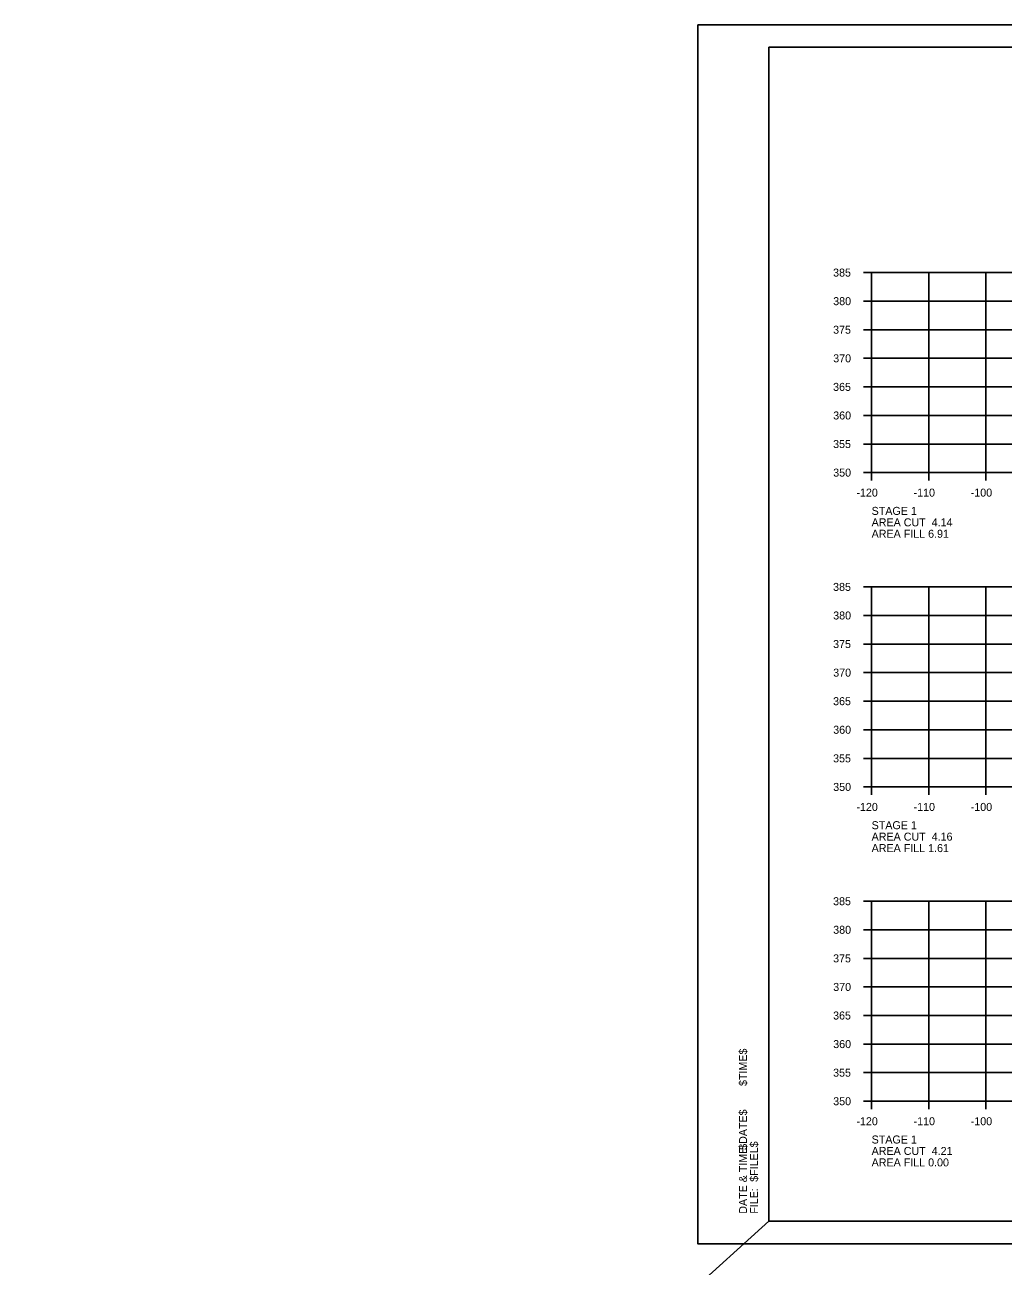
# Model space of a CAD drawing. Extents: x 1630712 to 1632516, y 782146 to 785403.
# Drawn here: x 1632064.8 to 1632236, y 783479.4 to 783696.6 of the extents above; entities that cross this region are included whole.
import ezdxf

# ---------------------------------------------------------------- set-up
doc = ezdxf.new("R2010")
doc.units = 0
for name, color, linetype in [('Default', 7, 'Continuous'), ('R_Axis', 7, 'Continuous'), ('R_Axis Annot', 7, 'Continuous'), ('R_Border', 7, 'Continuous'), ('R_Grid', 7, 'Continuous'), ('R_No Plot', 7, 'Continuous')]:
    doc.layers.add(name, color=color, linetype=linetype)

msp = doc.modelspace()

# ---------------------------------------------------------------- linework, layer by layer
at = {"layer": 'R_Axis'}
for p, q in [((1632211.56, 783653.28), (1632212.96, 783653.28)), ((1632212.96, 783618.28), (1632212.96, 783653.28)), ((1632211.56, 783648.28), (1632212.96, 783648.28)), ((1632211.56, 783643.28), (1632212.96, 783643.28)), ((1632211.56, 783638.28), (1632212.96, 783638.28)), ((1632211.56, 783633.28), (1632212.96, 783633.28)), ((1632211.56, 783628.28), (1632212.96, 783628.28)), ((1632211.56, 783623.28), (1632212.96, 783623.28)), ((1632211.56, 783618.28), (1632212.96, 783618.28)), ((1632212.96, 783618.28), (1632492.96, 783618.28)), ((1632212.96, 783616.88), (1632212.96, 783618.28)), ((1632222.96, 783616.88), (1632222.96, 783618.28)), ((1632232.96, 783616.88), (1632232.96, 783618.28)), ((1632211.56, 783598.28), (1632212.96, 783598.28)), ((1632212.96, 783563.28), (1632212.96, 783598.28)), ((1632211.56, 783593.28), (1632212.96, 783593.28)), ((1632211.56, 783588.28), (1632212.96, 783588.28)), ((1632211.56, 783583.28), (1632212.96, 783583.28)), ((1632211.56, 783578.28), (1632212.96, 783578.28)), ((1632211.56, 783573.28), (1632212.96, 783573.28)), ((1632211.56, 783568.28), (1632212.96, 783568.28)), ((1632211.56, 783563.28), (1632212.96, 783563.28)), ((1632212.96, 783563.28), (1632492.96, 783563.28)), ((1632212.96, 783561.88), (1632212.96, 783563.28)), ((1632222.96, 783561.88), (1632222.96, 783563.28)), ((1632232.96, 783561.88), (1632232.96, 783563.28)), ((1632211.56, 783543.28), (1632212.96, 783543.28)), ((1632212.96, 783508.28), (1632212.96, 783543.28)), ((1632211.56, 783538.28), (1632212.96, 783538.28)), ((1632211.56, 783533.28), (1632212.96, 783533.28)), ((1632211.56, 783528.28), (1632212.96, 783528.28)), ((1632211.56, 783523.28), (1632212.96, 783523.28)), ((1632211.56, 783518.28), (1632212.96, 783518.28)), ((1632211.56, 783513.28), (1632212.96, 783513.28)), ((1632211.56, 783508.28), (1632212.96, 783508.28)), ((1632212.96, 783508.28), (1632492.96, 783508.28)), ((1632212.96, 783506.88), (1632212.96, 783508.28)), ((1632222.96, 783506.88), (1632222.96, 783508.28)), ((1632232.96, 783506.88), (1632232.96, 783508.28))]:
    msp.add_line(p, q, dxfattribs=at)
at = {"layer": 'R_Border'}
for p, q in [((1632194.96, 783692.74), (1632511.14, 783692.74)), ((1632194.96, 783487.28), (1632194.96, 783692.74)), ((1632511.14, 783487.28), (1632194.96, 783487.28))]:
    msp.add_line(p, q, dxfattribs=at)
at = {"layer": 'R_Grid'}
for p, q in [((1632212.96, 783653.28), (1632492.96, 783653.28)), ((1632212.96, 783618.28), (1632212.96, 783653.28)), ((1632222.96, 783618.28), (1632222.96, 783653.28)), ((1632232.96, 783618.28), (1632232.96, 783653.28)), ((1632212.96, 783648.28), (1632492.96, 783648.28)), ((1632212.96, 783643.28), (1632492.96, 783643.28)), ((1632212.96, 783638.28), (1632492.96, 783638.28)), ((1632212.96, 783633.28), (1632492.96, 783633.28)), ((1632212.96, 783628.28), (1632492.96, 783628.28)), ((1632212.96, 783623.28), (1632492.96, 783623.28)), ((1632212.96, 783618.28), (1632492.96, 783618.28)), ((1632212.96, 783598.28), (1632492.96, 783598.28)), ((1632212.96, 783563.28), (1632212.96, 783598.28)), ((1632222.96, 783563.28), (1632222.96, 783598.28)), ((1632232.96, 783563.28), (1632232.96, 783598.28)), ((1632212.96, 783593.28), (1632492.96, 783593.28)), ((1632212.96, 783588.28), (1632492.96, 783588.28)), ((1632212.96, 783583.28), (1632492.96, 783583.28)), ((1632212.96, 783578.28), (1632492.96, 783578.28)), ((1632212.96, 783573.28), (1632492.96, 783573.28)), ((1632212.96, 783568.28), (1632492.96, 783568.28)), ((1632212.96, 783563.28), (1632492.96, 783563.28)), ((1632212.96, 783543.28), (1632492.96, 783543.28)), ((1632212.96, 783508.28), (1632212.96, 783543.28)), ((1632222.96, 783508.28), (1632222.96, 783543.28)), ((1632232.96, 783508.28), (1632232.96, 783543.28)), ((1632212.96, 783538.28), (1632492.96, 783538.28)), ((1632212.96, 783533.28), (1632492.96, 783533.28)), ((1632212.96, 783528.28), (1632492.96, 783528.28)), ((1632212.96, 783523.28), (1632492.96, 783523.28)), ((1632212.96, 783518.28), (1632492.96, 783518.28)), ((1632212.96, 783513.28), (1632492.96, 783513.28)), ((1632212.96, 783508.28), (1632492.96, 783508.28))]:
    msp.add_line(p, q, dxfattribs=at)
at = {"layer": 'R_No Plot'}
for p, q in [((1632182.56, 783696.63), (1632515.9, 783696.63)), ((1632194.96, 783487.28), (1630711.59, 782145.68)), ((1632182.56, 783483.3), (1632515.9, 783483.3))]:
    msp.add_line(p, q, dxfattribs=at)
msp.add_lwpolyline([(1632182.56, 783696.63), (1632515.9, 783696.63), (1632515.9, 783483.3), (1632182.56, 783483.3)], close=True, dxfattribs=at)

# ---------------------------------------------------------------- texts
at = {"layer": 'Default'}
for s, height, p in [('$TIME$', 1.397, (1632191.16, 783510.95)), ('$DATE$', 1.397, (1632191.16, 783499.78)), ('$FILEL$', 1.397, (1632193.08, 783494.19)), ('DATE & TIME:', 1.3968, (1632191.16, 783488.6)), ('FILE: ', 1.397, (1632193.08, 783488.6))]:
    msp.add_text(s, height=height, rotation=90, dxfattribs=at).set_placement(p)
at = {"layer": 'R_Axis'}
for p in [(1632212.96, 783618.28), (1632212.96, 783563.28), (1632212.96, 783508.28)]:
    msp.add_text('-', height=0.0001, dxfattribs=at).set_placement(p)
at = {"layer": 'R_Axis Annot'}
for s, p in [('385', (1632206.22, 783652.58)), ('380', (1632206.24, 783647.58)), ('375', (1632206.22, 783642.58)), ('370', (1632206.24, 783637.58)), ('365', (1632206.22, 783632.58)), ('360', (1632206.24, 783627.58)), ('355', (1632206.22, 783622.58)), ('350', (1632206.24, 783617.58)), ('-120', (1632210.3, 783614.08)), ('-110', (1632220.3, 783614.08)), ('-100', (1632230.3, 783614.08)), ('STAGE 1', (1632212.96, 783610.88)), ('AREA CUT  4.14', (1632212.96, 783608.88)), ('AREA FILL 6.91', (1632212.96, 783606.88)), ('385', (1632206.22, 783597.58)), ('380', (1632206.24, 783592.58)), ('375', (1632206.22, 783587.58)), ('370', (1632206.24, 783582.58)), ('365', (1632206.22, 783577.58)), ('360', (1632206.24, 783572.58)), ('355', (1632206.22, 783567.58)), ('350', (1632206.24, 783562.58)), ('-120', (1632210.3, 783559.08)), ('-110', (1632220.3, 783559.08)), ('-100', (1632230.3, 783559.08)), ('AREA CUT  4.16', (1632212.96, 783553.88)), ('STAGE 1', (1632212.96, 783555.88)), ('AREA FILL 1.61', (1632212.96, 783551.88)), ('385', (1632206.22, 783542.58)), ('380', (1632206.24, 783537.58)), ('375', (1632206.22, 783532.58)), ('370', (1632206.24, 783527.58)), ('365', (1632206.22, 783522.58)), ('360', (1632206.24, 783517.58)), ('355', (1632206.22, 783512.58)), ('350', (1632206.24, 783507.58)), ('-120', (1632210.3, 783504.08)), ('-110', (1632220.3, 783504.08)), ('-100', (1632230.3, 783504.08)), ('STAGE 1', (1632212.96, 783500.88)), ('AREA CUT  4.21', (1632212.96, 783498.88)), ('AREA FILL 0.00', (1632212.96, 783496.88))]:
    msp.add_text(s, height=1.4, dxfattribs=at).set_placement(p)

doc.saveas('drawing.dxf')
